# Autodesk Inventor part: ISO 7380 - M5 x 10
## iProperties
Created: 2006-04
Part Number: ISO 7380 - M5 x 10
Material: Сталь низкоуглеродистая
Description: Болт
Vendor: Autodesk Inc.
Document SubType Name: Modeling
Standard: ISO 7380
Designer: Калинин
Standards Organization: ISO
Language: ru-RU
Size Designation: M5 x 10
Categories: <MemberInstance Version="R10.0.0"><Categories><Category DisplayName="Крепежные изделия" InternalName="e4da775c-781d-43d5-af7c-5136215cf5a6" Mnemonic="FSTN"><Cat
Author: Калинин
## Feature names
1. Базовый элемент [Revolution]
2. Прорезь [Extrusion]
3. Сопряжение1 [Fillet]
4. Фаска1 [Chamfer]
